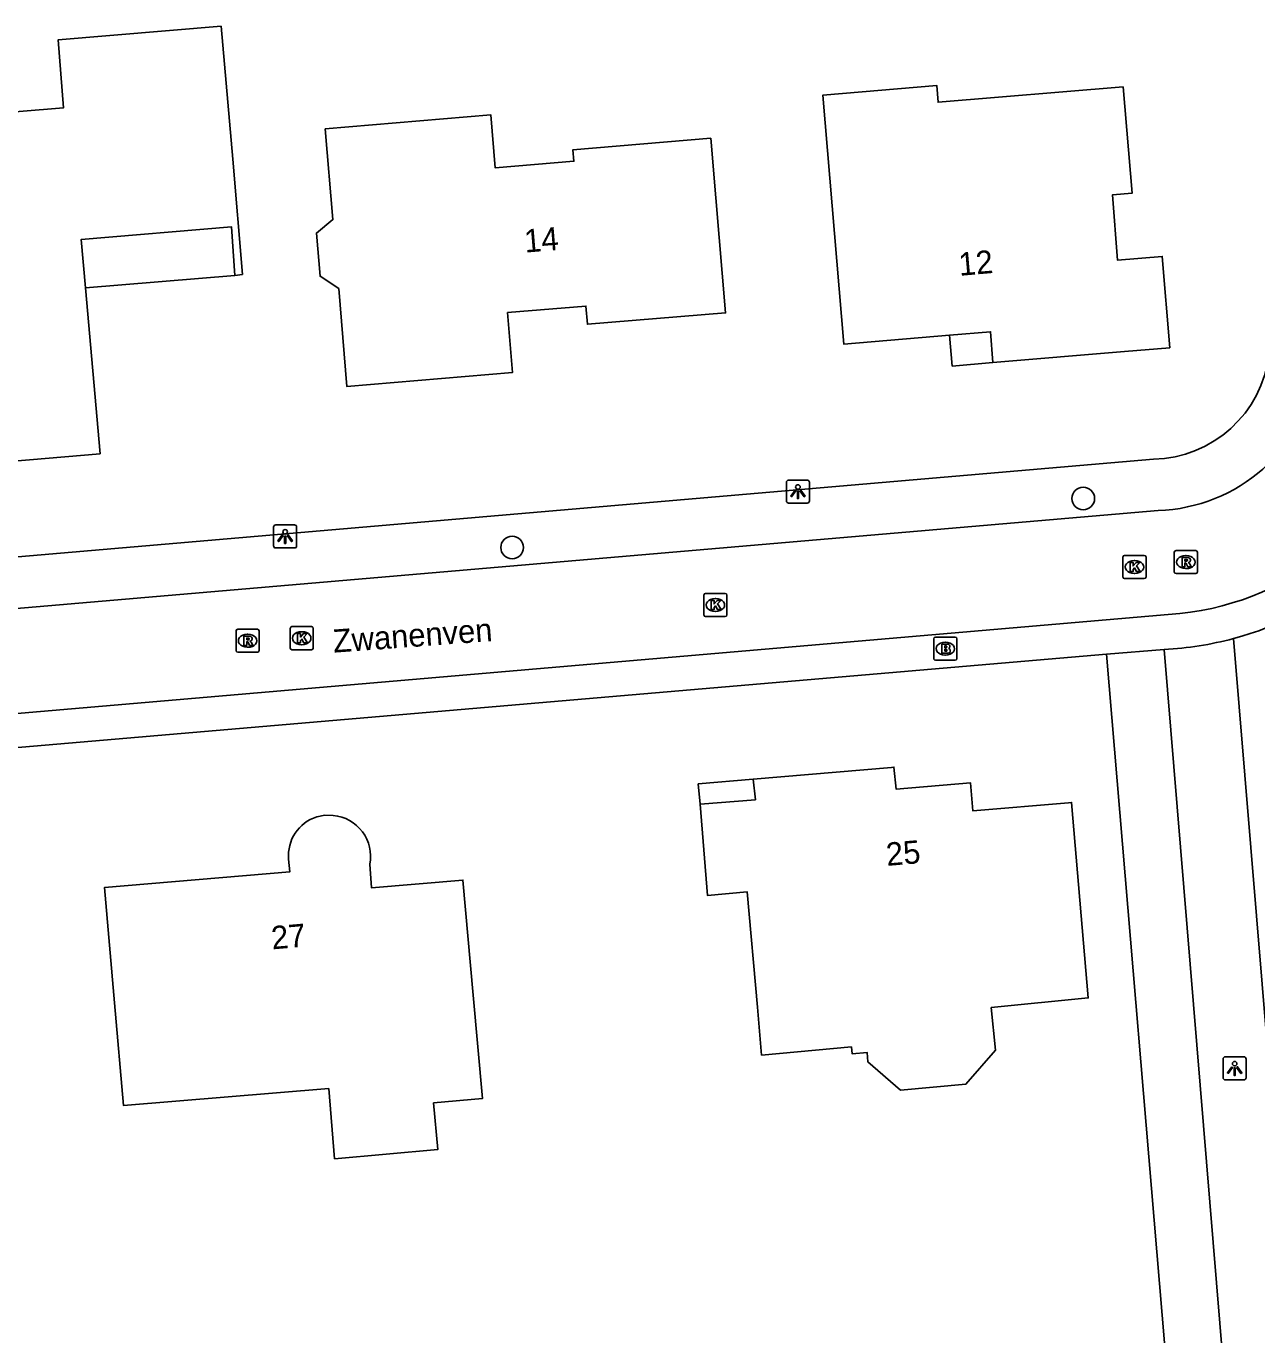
# Model space of a CAD drawing. Extents: x 163427 to 164190, y 380331 to 381641.
# Drawn here: x 164081.2 to 164134.4, y 381029.2 to 381085.8 of the extents above; entities that cross this region are included whole.
import ezdxf

# ---------------------------------------------------------------- set-up
doc = ezdxf.new("R2010")
doc.units = 0
for name, color, linetype in [('IMGEO_Boom', 7, 'Continuous'), ('IMGEO_Brandkraan', 7, 'Continuous'), ('IMGEO_Erf', 7, 'Continuous'), ('IMGEO_Groenvoorziening', 7, 'Continuous'), ('IMGEO_Kolk', 7, 'Continuous'), ('IMGEO_Lichtpunt', 7, 'Continuous'), ('IMGEO_Openbare_ruimte_label', 7, 'Continuous'), ('IMGEO_Pand', 7, 'Continuous'), ('IMGEO_Pand_nummerreeks', 7, 'Continuous'), ('IMGEO_Pand_overbouw', 7, 'Continuous'), ('IMGEO_Rijbaan_lokaal_open', 7, 'Continuous'), ('IMGEO_Rioolput', 7, 'Continuous'), ('IMGEO_Voetpad_open', 7, 'Continuous')]:
    doc.layers.add(name, color=color, linetype=linetype)

msp = doc.modelspace()

# ---------------------------------------------------------------- linework, layer by layer
at = {"layer": 'IMGEO_Boom'}
for centre in [(164126.898, 381065.393), (164102.189, 381063.272)]:
    msp.add_circle(centre, 0.489, dxfattribs=at)
at = {"layer": 'IMGEO_Brandkraan'}
for p, q in [((164120.43, 381058.468), (164120.43, 381059.32)), ((164120.505, 381059.394), (164121.357, 381059.394)), ((164121.431, 381059.32), (164121.431, 381058.468)), ((164120.918, 381059.174), (164120.943, 381059.174)), ((164121.357, 381058.394), (164120.505, 381058.394)), ((164120.941, 381058.614), (164120.916, 381058.614))]:
    msp.add_line(p, q, dxfattribs=at)
for points in [[(164120.43, 381058.468), (164120.43, 381059.32)], [(164120.505, 381059.394), (164121.357, 381059.394)], [(164121.431, 381059.32), (164121.431, 381058.468)], [(164120.778, 381059.094), (164120.778, 381058.694), (164120.991, 381058.694)], [(164121.009, 381059.094), (164120.778, 381059.094)], [(164120.957, 381059.013), (164120.903, 381059.013), (164120.903, 381058.937)], [(164120.903, 381058.937), (164120.956, 381058.937)], [(164120.965, 381058.861), (164120.903, 381058.861), (164120.903, 381058.78)], [(164120.903, 381058.78), (164120.965, 381058.78)], [(164121.357, 381058.394), (164120.505, 381058.394)]]:
    msp.add_lwpolyline(points, dxfattribs=at)
for centre, radius, start, end in [((164120.507, 381059.318), 0.0765, 91.552, 178.448), ((164120.507, 381059.318), 0.0765, 91.552, 178.448), ((164121.355, 381059.318), 0.0765, 1.552, 88.448), ((164121.355, 381059.318), 0.0765, 1.552, 88.448), ((164120.958, 381058.975), 0.0379, 267.8285, 90.9355), ((164120.966, 381058.82), 0.0404, 269.8759, 90.5077), ((164120.997, 381058.945), 0.251, 268.6676, 293.5347), ((164121.013, 381058.949), 0.145, 59.4692, 91.5367), ((164121.038, 381058.996), 0.0922, 285.5137, 58.1501), ((164121.043, 381058.804), 0.105, 301.3115, 78.989), ((164120.507, 381058.47), 0.0765, 181.552, 268.448), ((164120.507, 381058.47), 0.0765, 181.552, 268.448), ((164121.355, 381058.47), 0.0765, 271.552, 358.448), ((164121.355, 381058.47), 0.0765, 271.552, 358.448)]:
    msp.add_arc(centre, radius, start, end, dxfattribs=at)
for centre, major_axis, ratio, start_param, end_param in [((164120.917, 381058.894), (-0.387, 0.002), 0.722429, 4.712389, 7.853982), ((164120.942, 381058.894), (-0.39, 0.002), 0.717154, 1.570796, 4.712389)]:
    msp.add_ellipse(centre, major_axis=major_axis, ratio=ratio, start_param=start_param, end_param=end_param, dxfattribs=at)
at = {"layer": 'IMGEO_Erf'}
msp.add_lwpolyline([(164110.328, 381052.166), (164110.241, 381053.044), (164112.625, 381053.255)], dxfattribs=at)
at = {"layer": 'IMGEO_Groenvoorziening'}
msp.add_lwpolyline([(164130.664, 381025.955), (164127.903, 381058.65)], dxfattribs=at)
at = {"layer": 'IMGEO_Kolk'}
for p, q in [((164128.612, 381062.001), (164128.612, 381062.853)), ((164128.687, 381062.927), (164129.539, 381062.927)), ((164129.1, 381062.707), (164129.125, 381062.707)), ((164129.613, 381062.853), (164129.613, 381062.001)), ((164129.123, 381062.147), (164129.098, 381062.147)), ((164129.539, 381061.927), (164128.687, 381061.927)), ((164110.483, 381060.357), (164110.483, 381061.209)), ((164110.558, 381061.283), (164111.41, 381061.283)), ((164110.971, 381061.063), (164110.996, 381061.063)), ((164111.484, 381061.209), (164111.484, 381060.357)), ((164110.994, 381060.503), (164110.969, 381060.503)), ((164092.588, 381058.921), (164092.588, 381059.773)), ((164092.663, 381059.847), (164093.515, 381059.847)), ((164093.589, 381059.773), (164093.589, 381058.921)), ((164111.41, 381060.283), (164110.558, 381060.283)), ((164093.076, 381059.627), (164093.101, 381059.627)), ((164093.515, 381058.847), (164092.663, 381058.847)), ((164093.099, 381059.067), (164093.074, 381059.067))]:
    msp.add_line(p, q, dxfattribs=at)
for points in [[(164128.612, 381062.001), (164128.612, 381062.853)], [(164128.687, 381062.927), (164129.539, 381062.927)], [(164128.933, 381062.627), (164129.056, 381062.627), (164129.056, 381062.476), (164129.186, 381062.627), (164129.35, 381062.627), (164129.204, 381062.476), (164129.357, 381062.227), (164129.205, 381062.227), (164129.12, 381062.391), (164129.056, 381062.324), (164129.056, 381062.227), (164128.933, 381062.227), (164128.933, 381062.627)], [(164129.613, 381062.853), (164129.613, 381062.001)], [(164129.539, 381061.927), (164128.687, 381061.927)], [(164110.483, 381060.357), (164110.483, 381061.209)], [(164110.558, 381061.283), (164111.41, 381061.283)], [(164110.804, 381060.983), (164110.927, 381060.983), (164110.927, 381060.832), (164111.057, 381060.983), (164111.221, 381060.983), (164111.075, 381060.832), (164111.228, 381060.583), (164111.076, 381060.583), (164110.991, 381060.747), (164110.927, 381060.68), (164110.927, 381060.583), (164110.804, 381060.583), (164110.804, 381060.983)], [(164111.484, 381061.209), (164111.484, 381060.357)], [(164092.588, 381058.921), (164092.588, 381059.773)], [(164092.663, 381059.847), (164093.515, 381059.847)], [(164093.589, 381059.773), (164093.589, 381058.921)], [(164111.41, 381060.283), (164110.558, 381060.283)], [(164092.909, 381059.547), (164093.032, 381059.547), (164093.032, 381059.396), (164093.162, 381059.547), (164093.326, 381059.547), (164093.18, 381059.396), (164093.333, 381059.147), (164093.181, 381059.147), (164093.096, 381059.311), (164093.032, 381059.244), (164093.032, 381059.147), (164092.909, 381059.147), (164092.909, 381059.547)], [(164093.515, 381058.847), (164092.663, 381058.847)]]:
    msp.add_lwpolyline(points, dxfattribs=at)
for centre, start, end in [((164128.689, 381062.851), 91.552, 178.448), ((164128.689, 381062.851), 91.552, 178.448), ((164129.537, 381062.851), 1.552, 88.448), ((164129.537, 381062.851), 1.552, 88.448), ((164128.689, 381062.003), 181.552, 268.448), ((164128.689, 381062.003), 181.552, 268.448), ((164129.537, 381062.003), 271.552, 358.448), ((164129.537, 381062.003), 271.552, 358.448), ((164110.56, 381061.207), 91.552, 178.448), ((164110.56, 381061.207), 91.552, 178.448), ((164111.408, 381061.207), 1.552, 88.448), ((164111.408, 381061.207), 1.552, 88.448), ((164110.56, 381060.359), 181.552, 268.448), ((164110.56, 381060.359), 181.552, 268.448), ((164111.408, 381060.359), 271.552, 358.448), ((164111.408, 381060.359), 271.552, 358.448), ((164092.665, 381059.771), 91.552, 178.448), ((164092.665, 381059.771), 91.552, 178.448), ((164093.513, 381059.771), 1.552, 88.448), ((164093.513, 381059.771), 1.552, 88.448), ((164092.665, 381058.923), 181.552, 268.448), ((164092.665, 381058.923), 181.552, 268.448), ((164093.513, 381058.923), 271.552, 358.448), ((164093.513, 381058.923), 271.552, 358.448)]:
    msp.add_arc(centre, 0.0765, start, end, dxfattribs=at)
for centre, major_axis, ratio, start_param, end_param in [((164129.099, 381062.427), (-0.387, 0.002), 0.722429, 4.712389, 7.853982), ((164129.124, 381062.427), (-0.39, 0.002), 0.717154, 1.570796, 4.712389), ((164110.97, 381060.783), (-0.387, 0.002), 0.722429, 4.712389, 7.853982), ((164110.995, 381060.783), (-0.39, 0.002), 0.717154, 1.570796, 4.712389), ((164093.075, 381059.347), (-0.387, 0.002), 0.722429, 4.712389, 7.853982), ((164093.1, 381059.347), (-0.39, 0.002), 0.717154, 1.570796, 4.712389)]:
    msp.add_ellipse(centre, major_axis=major_axis, ratio=ratio, start_param=start_param, end_param=end_param, dxfattribs=at)
at = {"layer": 'IMGEO_Lichtpunt'}
for p, q in [((164114.056, 381066.092), (164114.056, 381065.285)), ((164114.056, 381066.092), (164114.056, 381065.285)), ((164114.958, 381066.187), (164114.15, 381066.187)), ((164114.958, 381066.187), (164114.15, 381066.187)), ((164115.052, 381065.285), (164115.052, 381066.092)), ((164115.052, 381065.285), (164115.052, 381066.092)), ((164114.15, 381065.191), (164114.958, 381065.191)), ((164114.15, 381065.191), (164114.958, 381065.191)), ((164091.873, 381064.152), (164091.873, 381063.345)), ((164091.873, 381064.152), (164091.873, 381063.345)), ((164092.775, 381064.247), (164091.967, 381064.247)), ((164092.775, 381064.247), (164091.967, 381064.247)), ((164092.869, 381063.345), (164092.869, 381064.152)), ((164092.869, 381063.345), (164092.869, 381064.152)), ((164091.967, 381063.251), (164092.775, 381063.251)), ((164091.967, 381063.251), (164092.775, 381063.251)), ((164132.947, 381041.143), (164132.947, 381040.336)), ((164132.947, 381041.143), (164132.947, 381040.336)), ((164133.849, 381041.238), (164133.041, 381041.238)), ((164133.849, 381041.238), (164133.041, 381041.238)), ((164133.943, 381040.336), (164133.943, 381041.143)), ((164133.943, 381040.336), (164133.943, 381041.143)), ((164133.041, 381040.242), (164133.849, 381040.242)), ((164133.041, 381040.242), (164133.849, 381040.242))]:
    msp.add_line(p, q, dxfattribs=at)
for points in [[(164114.43, 381065.756), (164114.469, 381065.728), (164114.281, 381065.466), (164114.243, 381065.493), (164114.43, 381065.756)], [(164114.532, 381065.708), (164114.579, 381065.708), (164114.579, 381065.386), (164114.532, 381065.386), (164114.532, 381065.708)], [(164114.642, 381065.728), (164114.68, 381065.755), (164114.867, 381065.493), (164114.828, 381065.465), (164114.642, 381065.728)], [(164092.247, 381063.816), (164092.286, 381063.788), (164092.098, 381063.526), (164092.06, 381063.553), (164092.247, 381063.816)], [(164092.349, 381063.768), (164092.396, 381063.768), (164092.396, 381063.446), (164092.349, 381063.446), (164092.349, 381063.768)], [(164092.459, 381063.788), (164092.497, 381063.815), (164092.684, 381063.553), (164092.645, 381063.525), (164092.459, 381063.788)], [(164133.321, 381040.807), (164133.36, 381040.779), (164133.172, 381040.517), (164133.134, 381040.544), (164133.321, 381040.807)], [(164133.423, 381040.759), (164133.47, 381040.759), (164133.47, 381040.437), (164133.423, 381040.437), (164133.423, 381040.759)], [(164133.533, 381040.779), (164133.571, 381040.806), (164133.758, 381040.544), (164133.719, 381040.516), (164133.533, 381040.779)]]:
    msp.add_lwpolyline(points, dxfattribs=at)
for centre in [(164114.555, 381065.89), (164092.372, 381063.95), (164133.446, 381040.941)]:
    msp.add_circle(centre, 0.0994, dxfattribs=at)
for centre, start, end in [((164114.15, 381066.092), 90, 180), ((164114.15, 381066.092), 90, 180), ((164114.958, 381066.092), 0, 90), ((164114.958, 381066.092), 0, 90), ((164114.15, 381065.285), 180, 270), ((164114.15, 381065.285), 180, 270), ((164114.958, 381065.285), 270, 0), ((164114.958, 381065.285), 270, 360), ((164091.967, 381064.152), 90, 180), ((164091.967, 381064.152), 90, 180), ((164092.775, 381064.152), 0, 90), ((164092.775, 381064.152), 0, 90), ((164091.967, 381063.345), 180, 270), ((164091.967, 381063.345), 180, 270), ((164092.775, 381063.345), 270, 0), ((164092.775, 381063.345), 270, 360), ((164133.041, 381041.143), 90, 180), ((164133.041, 381041.143), 90, 180), ((164133.849, 381041.143), 0, 90), ((164133.849, 381041.143), 0, 90), ((164133.041, 381040.336), 180, 270), ((164133.041, 381040.336), 180, 270), ((164133.849, 381040.336), 270, 0), ((164133.849, 381040.336), 270, 360)]:
    msp.add_arc(centre, 0.0946, start, end, dxfattribs=at)
at = {"layer": 'IMGEO_Pand'}
for points in [[(164089.611, 381085.824), (164090.102, 381080.067), (164090.526, 381075.085), (164090.195, 381075.041), (164090.045, 381077.144), (164083.551, 381076.596), (164083.735, 381074.499), (164084.364, 381067.326), (164079.765, 381066.927), (164079.654, 381068.237), (164072.528, 381067.634), (164072.114, 381072.617), (164071.575, 381079.097), (164075.808, 381079.449), (164075.621, 381081.7), (164082.79, 381082.296), (164082.546, 381085.226), (164089.611, 381085.824)], [(164128.626, 381083.206), (164129.007, 381078.594), (164128.161, 381078.524), (164128.378, 381075.704), (164130.313, 381075.864), (164130.641, 381071.913), (164128.682, 381071.75), (164122.983, 381071.277), (164122.89, 381072.607), (164121.113, 381072.454), (164116.543, 381072.062), (164115.633, 381082.843), (164120.559, 381083.258), (164120.62, 381082.53), (164128.626, 381083.206)], [(164110.793, 381080.978), (164111.009, 381078.401), (164111.427, 381073.418), (164105.45, 381072.927), (164105.385, 381073.714), (164101.998, 381073.436), (164102.211, 381070.846), (164095.045, 381070.23), (164094.689, 381074.473), (164093.881, 381075.003), (164093.724, 381076.874), (164094.439, 381077.454), (164094.109, 381081.381), (164101.272, 381081.982), (164101.464, 381079.694), (164104.866, 381079.98), (164104.824, 381080.477), (164110.793, 381080.978)], [(164112.625, 381053.255), (164118.6, 381053.76), (164118.71, 381053.769), (164118.803, 381052.821), (164122.018, 381053.095), (164122.122, 381051.877), (164126.256, 381052.229), (164126.395, 381052.241), (164127.111, 381043.784), (164122.914, 381043.365), (164123.098, 381041.521), (164121.821, 381040.057), (164118.992, 381039.794), (164117.585, 381041.02), (164117.548, 381041.429), (164116.899, 381041.37), (164116.872, 381041.669), (164112.981, 381041.315), (164112.799, 381043.392), (164112.361, 381048.372), (164110.637, 381048.221), (164110.328, 381052.166)], [(164112.625, 381053.255), (164112.712, 381052.361), (164110.328, 381052.166)], [(164093.736, 381051.621), (164094.093, 381051.686), (164094.456, 381051.678)], [(164096.031, 381049.574), (164096.108, 381048.543), (164100.063, 381048.885), (164100.507, 381043.905), (164100.906, 381039.431), (164098.794, 381039.243), (164098.974, 381037.225), (164094.513, 381036.827), (164094.26, 381039.866), (164085.381, 381039.127), (164084.99, 381043.576), (164084.552, 381048.556), (164092.569, 381049.24), (164092.522, 381049.789)]]:
    msp.add_lwpolyline(points, dxfattribs=at)
for centre, radius, start, end in [((164094.28, 381049.942), 1.765, 107.9585, 184.9795), ((164094.302, 381049.921), 1.763, 348.6339, 85.0012)]:
    msp.add_arc(centre, radius, start, end, dxfattribs=at)
at = {"layer": 'IMGEO_Pand_overbouw'}
for points in [[(164090.045, 381077.144), (164083.551, 381076.596), (164083.735, 381074.499), (164090.195, 381075.041)], [(164122.983, 381071.277), (164122.89, 381072.607), (164121.113, 381072.454), (164121.23, 381071.122)], [(164110.328, 381052.166), (164112.712, 381052.361), (164112.625, 381053.255), (164110.241, 381053.044)]]:
    msp.add_lwpolyline(points, close=True, dxfattribs=at)
at = {"layer": 'IMGEO_Rijbaan_lokaal_open'}
for points in [[(164050.175, 381058.005), (164130.134, 381064.866)], [(164131.078, 381060.415), (164050.427, 381053.487)]]:
    msp.add_lwpolyline(points, dxfattribs=at)
for centre, radius, start, end in [((164129.86, 381072.174), 7.313, 272.1455, 350.1456), ((164129.901, 381072.152), 11.795, 275.7272, 346.4702)]:
    msp.add_arc(centre, radius, start, end, dxfattribs=at)
at = {"layer": 'IMGEO_Rioolput'}
for p, q in [((164130.837, 381062.214), (164130.837, 381063.066)), ((164130.912, 381063.14), (164131.764, 381063.14)), ((164131.325, 381062.92), (164131.35, 381062.92)), ((164131.838, 381063.066), (164131.838, 381062.214)), ((164131.764, 381062.14), (164130.912, 381062.14)), ((164131.348, 381062.36), (164131.323, 381062.36)), ((164090.247, 381058.811), (164090.247, 381059.663)), ((164090.322, 381059.737), (164091.174, 381059.737)), ((164090.735, 381059.517), (164090.76, 381059.517)), ((164091.248, 381059.663), (164091.248, 381058.811)), ((164091.174, 381058.737), (164090.322, 381058.737)), ((164090.758, 381058.957), (164090.733, 381058.957))]:
    msp.add_line(p, q, dxfattribs=at)
for points in [[(164130.837, 381062.214), (164130.837, 381063.066)], [(164130.912, 381063.14), (164131.764, 381063.14)], [(164131.426, 381062.838), (164131.174, 381062.84), (164131.174, 381062.44)], [(164131.174, 381062.44), (164131.298, 381062.44), (164131.298, 381062.602), (164131.309, 381062.602)], [(164131.352, 381062.759), (164131.298, 381062.759), (164131.298, 381062.678)], [(164131.298, 381062.678), (164131.35, 381062.678)], [(164131.838, 381063.066), (164131.838, 381062.214)], [(164131.764, 381062.14), (164130.912, 381062.14)], [(164131.356, 381062.573), (164131.427, 381062.44), (164131.567, 381062.44), (164131.502, 381062.566)], [(164090.247, 381058.811), (164090.247, 381059.663)], [(164090.322, 381059.737), (164091.174, 381059.737)], [(164090.836, 381059.435), (164090.584, 381059.437), (164090.584, 381059.037)], [(164090.762, 381059.356), (164090.708, 381059.356), (164090.708, 381059.275)], [(164090.708, 381059.275), (164090.76, 381059.275)], [(164091.248, 381059.663), (164091.248, 381058.811)], [(164091.174, 381058.737), (164090.322, 381058.737)], [(164090.584, 381059.037), (164090.708, 381059.037), (164090.708, 381059.199), (164090.719, 381059.199)], [(164090.766, 381059.17), (164090.837, 381059.037), (164090.977, 381059.037), (164090.912, 381059.163)]]:
    msp.add_lwpolyline(points, dxfattribs=at)
for centre, radius, start, end in [((164130.914, 381063.064), 0.0765, 91.552, 178.448), ((164130.914, 381063.064), 0.0765, 91.552, 178.448), ((164131.308, 381062.549), 0.0533, 26.0293, 88.6989), ((164131.334, 381062.867), 0.19, 274.7715, 282.9687), ((164131.358, 381062.663), 0.0964, 77.0061, 93.1865), ((164131.372, 381062.72), 0.0378, 276.6634, 79.6772), ((164131.425, 381062.728), 0.109, 350.3612, 89.416), ((164131.423, 381062.728), 0.112, 277.5842, 350.9817), ((164131.407, 381062.513), 0.108, 29.5134, 73.7905), ((164131.762, 381063.064), 0.0765, 1.552, 88.448), ((164131.762, 381063.064), 0.0765, 1.552, 88.448), ((164130.914, 381062.216), 0.0765, 181.552, 268.448), ((164130.914, 381062.216), 0.0765, 181.552, 268.448), ((164131.762, 381062.216), 0.0765, 271.552, 358.448), ((164131.762, 381062.216), 0.0765, 271.552, 358.448), ((164090.324, 381059.661), 0.0765, 91.552, 178.448), ((164090.324, 381059.661), 0.0765, 91.552, 178.448), ((164090.744, 381059.464), 0.19, 274.7715, 282.9687), ((164090.768, 381059.26), 0.0964, 77.0061, 93.1865), ((164090.782, 381059.317), 0.0378, 276.6634, 79.6772), ((164090.835, 381059.325), 0.109, 350.3612, 89.416), ((164090.833, 381059.325), 0.112, 277.5842, 350.9817), ((164090.817, 381059.11), 0.108, 29.5134, 73.7905), ((164091.172, 381059.661), 0.0765, 1.552, 88.448), ((164091.172, 381059.661), 0.0765, 1.552, 88.448), ((164090.324, 381058.813), 0.0765, 181.552, 268.448), ((164090.324, 381058.813), 0.0765, 181.552, 268.448), ((164090.718, 381059.146), 0.0533, 26.0293, 88.6989), ((164091.172, 381058.813), 0.0765, 271.552, 358.448), ((164091.172, 381058.813), 0.0765, 271.552, 358.448)]:
    msp.add_arc(centre, radius, start, end, dxfattribs=at)
for centre, major_axis, ratio, start_param, end_param in [((164131.324, 381062.64), (-0.387, 0.002), 0.722429, 4.712389, 7.853982), ((164131.349, 381062.64), (-0.39, 0.002), 0.717154, 1.570796, 4.712389), ((164090.734, 381059.237), (-0.387, 0.002), 0.722429, 4.712389, 7.853982), ((164090.759, 381059.237), (-0.39, 0.002), 0.717154, 1.570796, 4.712389)]:
    msp.add_ellipse(centre, major_axis=major_axis, ratio=ratio, start_param=start_param, end_param=end_param, dxfattribs=at)
at = {"layer": 'IMGEO_Voetpad_open'}
for points in [[(164050.279, 381060.237), (164129.935, 381067.097)], [(164135.637, 381032.385), (164133.392, 381059.329)], [(164127.903, 381058.65), (164077.934, 381054.369), (164053.22, 381052.357), (164049.464, 381051.933)], [(164127.903, 381058.65), (164130.402, 381058.864)], [(164130.402, 381058.864), (164133.225, 381024.655)]]:
    msp.add_lwpolyline(points, dxfattribs=at)
for centre, radius, start, end in [((164129.846, 381072.209), 5.113, 271.0013, 353.5552), ((164130.06, 381071.956), 13.059, 284.7814, 311.5453), ((164129.688, 381073.299), 14.452, 272.8307, 284.8488)]:
    msp.add_arc(centre, radius, start, end, dxfattribs=at)

# ---------------------------------------------------------------- texts
at = {"layer": 'IMGEO_Openbare_ruimte_label'}
msp.add_text('Zwanenven', height=1, rotation=4.1877, dxfattribs=at).set_placement((164094.471, 381058.72))
at = {"layer": 'IMGEO_Pand_nummerreeks'}
for s, rotation, p in [('14', 4.6925, (164102.752, 381076.027)), ('12', 4.9102, (164121.547, 381075.022)), ('25', 4.8713, (164118.407, 381049.495)), ('27', 4.8759, (164091.813, 381045.883))]:
    msp.add_text(s, height=1, rotation=rotation, dxfattribs=at).set_placement(p)

doc.saveas('drawing.dxf')
